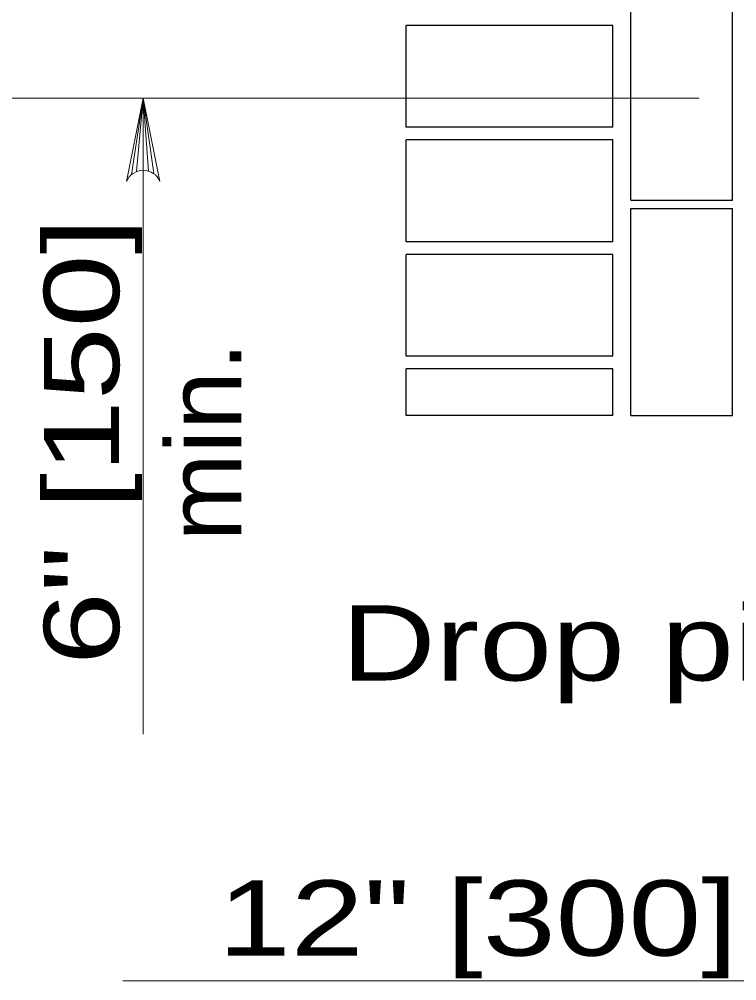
# Model space of a CAD drawing. Extents: x 750.7 to 784.7, y 860.1 to 882.1.
# Drawn here: x 766.797 to 768.322, y 868.438 to 870.48 of the extents above; entities that cross this region are included whole.
import ezdxf
from ezdxf.enums import TextEntityAlignment as Align

# ---------------------------------------------------------------- set-up
doc = ezdxf.new("R2010")
doc.units = 0
doc.header["$LTSCALE"] = 0.064
doc.layers.add('1', color=7, linetype='Continuous', lineweight=13)

msp = doc.modelspace()

# ---------------------------------------------------------------- linework, layer by layer
at = {"layer": '1', "lineweight": 25}
for p, q in [((768.09642, 870.09625), (768.09642, 870.54925)), ((768.31267, 870.09625), (768.31267, 870.54925)), ((767.61883, 870.25067), (767.61883, 870.46692)), ((768.05842, 870.46692), (767.61883, 870.46692)), ((768.05842, 870.25067), (768.05842, 870.46692)), ((768.05842, 870.25067), (767.61883, 870.25067)), ((768.05842, 870.22383), (767.61883, 870.22383)), ((768.05842, 870.17283), (768.05842, 870.22383)), ((768.05842, 870.00758), (768.05842, 870.17283)), ((768.09642, 870.09625), (768.31267, 870.09625)), ((768.09642, 869.63858), (768.09642, 870.07817)), ((768.09642, 870.07817), (768.31267, 870.07817)), ((768.31267, 869.63858), (768.31267, 870.07817)), ((768.05842, 869.98075), (767.61883, 869.98075)), ((767.61883, 869.7645), (767.61883, 869.98075)), ((768.05842, 869.7645), (768.05842, 869.98075)), ((768.05842, 869.7645), (767.61883, 869.7645)), ((768.05842, 869.73767), (767.61883, 869.73767)), ((767.61883, 869.63858), (767.61883, 869.73767)), ((768.05842, 869.63858), (768.05842, 869.73767)), ((768.05842, 869.63858), (767.61883, 869.63858)), ((768.09642, 869.63858), (768.31267, 869.63858))]:
    msp.add_line(p, q, dxfattribs=at)
at = {"layer": '1'}
for p, q in [((768.24217, 870.31258), (766.35725, 870.31258)), ((767.03558, 870.15033), (767.06042, 870.31258)), ((767.046, 870.1565), (767.06042, 870.31258)), ((767.06042, 870.31325), (767.06042, 868.96117)), ((767.06042, 870.15933), (767.06042, 870.31258)), ((767.07175, 870.15767), (767.06042, 870.31258)), ((767.08283, 870.15225), (767.06042, 870.31258)), ((769.50358, 868.4375), (767.01692, 868.4375))]:
    msp.add_line(p, q, dxfattribs=at)
msp.add_lwpolyline([(767.025, 870.1355), (767.06042, 870.31258), (767.09583, 870.1355)], dxfattribs=at)
at = {"layer": '1', "lineweight": 25}
msp.add_lwpolyline([(768.05842, 870.00758), (767.61883, 870.00758), (767.61883, 870.22383)], dxfattribs=at)
at = {"layer": '1'}
msp.add_arc((767.06043, 870.12118), 0.03822, 22.08782, 157.91395, dxfattribs=at)

# ---------------------------------------------------------------- texts
for s, width, p in [('6" [150]', 1.3, (767.00917, 869.58308)), ('min.', 1.05, (767.26917, 869.58308))]:
    msp.add_text(s, height=0.16, rotation=90, dxfattribs=dict(at, width=width)).set_placement(p, align=Align.CENTER)
at = {"layer": '1', "width": 1.3}
msp.add_text('Drop pipe', height=0.16, dxfattribs=at).set_placement((767.48092, 869.07542))
msp.add_text('12" [300] min.', height=0.16, dxfattribs=at).set_placement((768.07283, 868.49083), align=Align.CENTER)

doc.saveas('drawing.dxf')
